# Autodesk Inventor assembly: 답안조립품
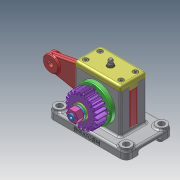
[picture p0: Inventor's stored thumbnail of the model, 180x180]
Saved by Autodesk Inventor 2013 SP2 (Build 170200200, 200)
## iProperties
Created: 2025-04
Part Number: 답안조립품
Document SubType Name: Assembly
Designer: i
Author: i
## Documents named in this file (15)
- C:\Users\i\Documents\Inventor\750404V1009\답안조립품.iam
- C:\Users\i\Documents\Inventor\750404V1009\본체.ipt
- C:\Users\i\Documents\Inventor\750404V1009\750404V1009\그리스 니플 M6x0.75.ipt
- C:\Users\i\Documents\Inventor\750404V1009\750404V1009\로드.ipt
- C:\Users\i\Documents\Inventor\750404V1009\750404V1009\스퍼기어.ipt
- C:\Users\i\Documents\Inventor\750404V1009\750404V1009\스프링와셔 M10.ipt
- C:\Users\i\Documents\Inventor\750404V1009\750404V1009\실링.ipt
- C:\Users\i\Documents\Inventor\750404V1009\750404V1009\앞커버.ipt
- C:\Users\i\Documents\Inventor\750404V1009\750404V1009\윗커버.ipt
- C:\Users\i\Documents\Inventor\750404V1009\750404V1009\육각 너트 M10.ipt
- C:\Users\i\Documents\Inventor\750404V1009\750404V1009\육각 소켓 머리 볼트 M4x10.ipt
- C:\Users\i\Documents\Inventor\750404V1009\750404V1009\편심축.ipt
- C:\Users\i\Documents\Inventor\750404V1009\750404V1009\평와셔 M10.ipt
- C:\Users\i\Documents\Inventor\750404V1009\750404V1009\평행키 4x4x10.ipt
- C:\Users\i\Documents\Inventor\750404V1009\750404V1009\플랜지 오일레스 부시.ipt
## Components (3 placed, 2 different names)
1. 그리스 니플 M6x0.75:1 — 각도:6
2. 플랜지 오일레스 부시:1
3. 플랜지 오일레스 부시:2
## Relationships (1: Angle 1)
- 각도:6 [Angle]: 그리스 니플 M6x0.75:1
